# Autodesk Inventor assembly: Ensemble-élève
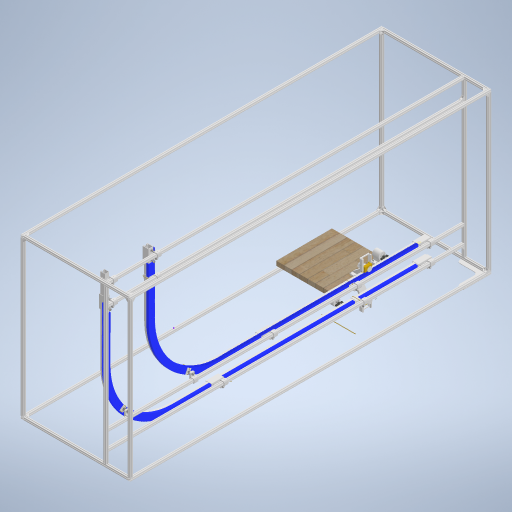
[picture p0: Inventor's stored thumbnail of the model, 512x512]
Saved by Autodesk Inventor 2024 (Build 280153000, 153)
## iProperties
Created: 2026-03
Part Number: Ensemble-élève
Document SubType Name: Assembly
Designer: bruno
Author: bruno
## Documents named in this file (7)
- C:\Users\bruno\Documents\1-Cours-2025-26\Concours général-Relecture\Oral\Version finale\Dossier élèves\Ensemble-élève.iam
- C:\Users\bruno\Documents\1-Cours-2025-26\Concours général-Relecture\Oral\Version finale\Dossier élèves\Structure\structure.iam
- C:\Users\bruno\Documents\1-Cours-2025-26\Concours général-Relecture\Oral\Version finale\Dossier élèves\Cloison\panneau articulé.iam
- C:\Users\bruno\Documents\1-Cours-2025-26\Concours général-Relecture\Oral\Version finale\Dossier élèves\0235A\0235A complet.iam
- C:\Users\bruno\Documents\1-Cours-2025-26\Concours général-Relecture\Oral\Version finale\Dossier élèves\Moteur\Ensemble2-moteur.iam
- C:\Users\bruno\Documents\1-Cours-2025-26\Concours général-Relecture\Oral\Version finale\Dossier élèves\Moteur\Ensemble-pignon-40.iam
- C:\Users\bruno\Documents\Inventor\Content Center Files\R2024\fr-FR\BS 3673(4)\BS 3673_1 - S010M.ipt
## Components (9 placed, 6 different names)
1. structure:1 [sub-assembly] — Angle:1, Tangente:1, Angle:2, Placage:5, Tangente:2, Placage:6, Tangente:3, Tangente:4
2. panneau articulé:1 [sub-assembly] — Placage:1, Placage:2, Placage:7, Placage:8, Placage:9, Placage:10, Placage:11
3. 0235A complet:1 [sub-assembly] — Placage:2, Angle:1, Placage:5, Tangente:2, Placage:7
4. 0235A complet:2 [sub-assembly] — Placage:1, Tangente:1, Angle:2, Placage:6
5. Ensemble2-moteur:1 [sub-assembly] — Placage:10, Placage:11, Logement:1
6. Ensemble2-moteur:2 [sub-assembly] — Placage:8, Placage:9, Logement:2
7. Ensemble-pignon-40:1 [sub-assembly] — Logement:1, Tangente:3
8. Ensemble-pignon-40:2 [sub-assembly] — Logement:2, Tangente:4
9. BS 3673 : Pièce 1 - Métrique S010M:1
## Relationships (17: Mate 9, Tangent 4, Angle 2, Insert 2)
- Placage:1 [Mate]: panneau articulé:1 ↔ 0235A complet:2
- Placage:2 [Mate]: panneau articulé:1 ↔ 0235A complet:1
- Angle:1: structure:1 ↔ 0235A complet:1
- Tangente:1: structure:1 ↔ 0235A complet:2
- Angle:2: structure:1 ↔ 0235A complet:2
- Placage:5 [Mate]: structure:1 ↔ 0235A complet:1
- Tangente:2: structure:1 ↔ 0235A complet:1
- Placage:6 [Mate]: structure:1 ↔ 0235A complet:2
- Placage:7 [Mate]: panneau articulé:1 ↔ 0235A complet:1
- Placage:8 [Mate]: panneau articulé:1 ↔ Ensemble2-moteur:2
- Placage:9 [Mate]: panneau articulé:1 ↔ Ensemble2-moteur:2
- Placage:10 [Mate]: panneau articulé:1 ↔ Ensemble2-moteur:1
- Placage:11 [Mate]: panneau articulé:1 ↔ Ensemble2-moteur:1
- Logement:1 [Insert]: Ensemble2-moteur:1 ↔ Ensemble-pignon-40:1
- Logement:2 [Insert]: Ensemble2-moteur:2 ↔ Ensemble-pignon-40:2
- Tangente:3: structure:1 ↔ Ensemble-pignon-40:1
- Tangente:4: structure:1 ↔ Ensemble-pignon-40:2
